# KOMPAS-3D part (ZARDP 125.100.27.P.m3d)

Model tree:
1. Булева операция:1
2. Булева операция:2
3. Булева операция:3
4. Булева операция:4
5. Булева операция:5
6. Булева операция:6
7. Булева операция:7
8. Булева операция:8
9. Булева операция:9
10. Булева операция:10
11. Булева операция:11
12. Булева операция:12
13. Булева операция:13
14. Булева операция:14
15. Булева операция:15
16. Булева операция:16
17. Булева операция:17
18. Булева операция:18
19. Булева операция:19
20. Булева операция:20
21. Булева операция:21
22. Булева операция:22
23. Булева операция:23
24. Булева операция:24
25. Булева операция:25
26. Булева операция:26
27. Булева операция:27
28. Булева операция:28
29. Булева операция:29
30. Булева операция:30
31. Булева операция:31
32. Булева операция:32  (labels: C:\Program Files\ASCON\KOMPAS-3D V13\Sys\graphic.lyt)
